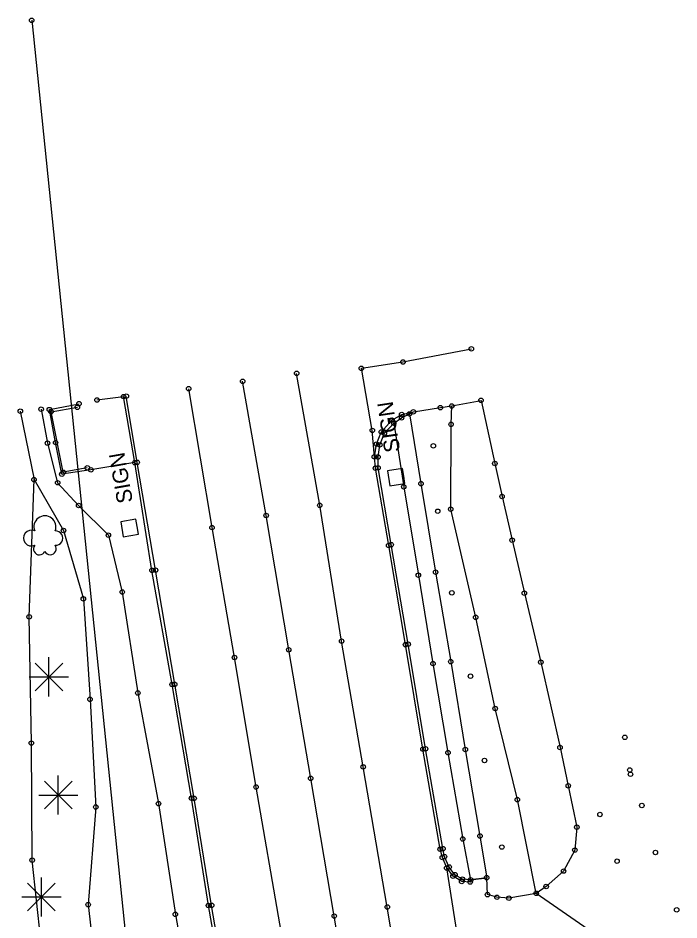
# Model space of a CAD drawing. Extents: x 21481721 to 21494985, y 8063982 to 8084842.
# Drawn here: x 21487996.8 to 21488144.4, y 8075524.3 to 8075725.6 of the extents above; entities that cross this region are included whole.
import ezdxf

# ---------------------------------------------------------------- set-up
doc = ezdxf.new("R2010")
doc.units = 0
for name, color, linetype in [('Building', 7, 'Continuous'), ('Drainage', 7, 'Continuous'), ('EXT_BL', 7, 'Continuous'), ('EXT_C', 7, 'Continuous'), ('EXT_CON', 7, 'Continuous'), ('EXT_CU', 7, 'Continuous'), ('EXT_GU', 7, 'Continuous'), ('EXT_SWK', 7, 'Continuous'), ('SurNaturalCells', 7, 'Continuous'), ('SurPointsNonDTM', 7, 'Continuous'), ('SurRoadPoints', 7, 'Continuous'), ('SurSurveyPoints', 7, 'Continuous')]:
    doc.layers.add(name, color=color, linetype=linetype)

msp = doc.modelspace()

# ---------------------------------------------------------------- linework, layer by layer
at = {"layer": 'Building'}
msp.add_lwpolyline([(21488012.29, 8075625.22), (21488006.93, 8075624.24), (21488004.19, 8075637.76), (21488010.07, 8075638.74)], dxfattribs=at)
at = {"layer": 'Drainage'}
msp.add_lwpolyline([(21487999.88, 8075725.11), (21488024.12, 8075488.97)], dxfattribs=at)
at = {"layer": 'EXT_BL'}
for points in [[(21488103.19, 8075384.64), (21488099.05, 8075409.52), (21488096.27, 8075426.26), (21488095.42, 8075431.16), (21488094.63, 8075436.26), (21488089.97, 8075465.06), (21488084.44, 8075496.32), (21488079.25, 8075527.2), (21488073.87, 8075558.48), (21488069.05, 8075586.55), (21488064.17, 8075616.87), (21488059.01, 8075646.31)], [(21488078.47, 8075383.41), (21488075.34, 8075404.11), (21488072.38, 8075422.27), (21488071.48, 8075427.29), (21488070.62, 8075432.22), (21488065.88, 8075460.89), (21488060.66, 8075491.95), (21488055.28, 8075523.45), (21488049.96, 8075553.99), (21488045.13, 8075582.91), (21488040.13, 8075611.89), (21488034.92, 8075642.89)], [(21487997.33, 8075637.86), (21488000.4, 8075622.59), (21488006.98, 8075611.23), (21488011.41, 8075595.98), (21488012.9, 8075573.56), (21488014.18, 8075549.52), (21488012.49, 8075527.74), (21488015.17, 8075504.07)], [(21488001.98, 8075638.33), (21488003.4, 8075630.75), (21488005.67, 8075621.9), (21488010.36, 8075616.83), (21488017, 8075610.19), (21488020.09, 8075597.51), (21488023.57, 8075574.98), (21488028.19, 8075550.29), (21488031.95, 8075525.57), (21488036.19, 8075501.31), (21488039.36, 8075478.97), (21488044.58, 8075454.12), (21488049.02, 8075430.98), (21488050.89, 8075415.65), (21488053.69, 8075400.59), (21488055.28, 8075390.26), (21488059.94, 8075389.21)], [(21488017.28, 8075334.44), (21488016.02, 8075354.14), (21488012.44, 8075377.08), (21488008.44, 8075400.23), (21488006.48, 8075416.6), (21488000.73, 8075439.94), (21487998.96, 8075464.83), (21488002.87, 8075510.86), (21487999.99, 8075537.67), (21487999.81, 8075563.8), (21487999.31, 8075591.97), (21488000.4, 8075622.59)]]:
    msp.add_lwpolyline(points, dxfattribs=at)
at = {"layer": 'EXT_C'}
msp.add_lwpolyline([(21488091.11, 8075383.97), (21488087.22, 8075407.72), (21488084.32, 8075424.42), (21488083.54, 8075429.23), (21488082.68, 8075434.22), (21488078.06, 8075462.54), (21488072.58, 8075494.16), (21488067.41, 8075525.19), (21488062.16, 8075555.92), (21488057.25, 8075584.62), (21488052.2, 8075614.6), (21488046.96, 8075644.54)], dxfattribs=at)
at = {"layer": 'EXT_CON'}
for points in [[(21488073.46, 8075647.44), (21488082.75, 8075648.86), (21488098.01, 8075651.79)], [(21488085.07, 8075637.72), (21488091.09, 8075638.67), (21488093.64, 8075639.04)], [(21488107.48, 8075477.19), (21488109.54, 8075479.35), (21488111.61, 8075481.3), (21488114.42, 8075483.32), (21488118.82, 8075485.97), (21488129.83, 8075487.79), (21488128.33, 8075497.11), (21488126.2, 8075509.77), (21488124.12, 8075522.17), (21488112.49, 8075530.26), (21488106.39, 8075529.17), (21488103.72, 8075529.39), (21488101.61, 8075529.97), (21488101.44, 8075533.75), (21488097.85, 8075533.27), (21488097.74, 8075532.79)]]:
    msp.add_lwpolyline(points, dxfattribs=at)
msp.add_lwpolyline([(21488112.49, 8075530.26), (21488108.29, 8075551.18), (21488103.34, 8075571.5), (21488098.98, 8075591.86), (21488093.41, 8075616.01), (21488093.49, 8075634.94), (21488093.64, 8075639.04), (21488100.18, 8075640.29), (21488103.27, 8075626.2), (21488104.87, 8075618.83), (21488107.11, 8075609.08), (21488109.85, 8075597.25), (21488113.51, 8075581.85), (21488117.8, 8075562.82), (21488119.64, 8075554.27), (21488121.56, 8075545.04), (21488121.12, 8075539.92), (21488118.6, 8075535.23), (21488114.71, 8075531.79)], close=True, dxfattribs=at)
at = {"layer": 'EXT_CU'}
for points in [[(21488055.5, 8075419.32), (21488055.16, 8075424.86), (21488054.72, 8075429.57), (21488053.7, 8075442.99), (21488050.75, 8075460.09), (21488047.06, 8075482.72), (21488043.37, 8075504.61), (21488039.33, 8075527.55), (21488035.55, 8075551.49), (21488031.22, 8075576.87), (21488026.72, 8075602.34), (21488022.88, 8075626.39), (21488020.38, 8075641.13)], [(21488097.85, 8075533.27), (21488096.02, 8075533.44), (21488094.35, 8075534.42), (21488093.06, 8075536.14), (21488092.02, 8075538.44), (21488091.68, 8075540.24), (21488087.8, 8075562.52), (21488083.91, 8075585.86), (21488080.11, 8075608.09), (21488077.18, 8075625.23), (21488077.18, 8075627.64), (21488077.57, 8075630.35), (21488078.61, 8075632.96), (21488080.69, 8075635.19), (21488082.44, 8075636.37), (21488085.07, 8075637.72)]]:
    msp.add_lwpolyline(points, dxfattribs=at)
at = {"layer": 'EXT_GU'}
for points in [[(21488076.36, 8075627.68), (21488075.91, 8075633.58), (21488073.46, 8075647.44)], [(21488056.32, 8075419.59), (21488055.81, 8075425.01), (21488055.29, 8075429.62), (21488055.5, 8075429.95), (21488054.21, 8075443.21), (21488051.26, 8075460.11), (21488047.59, 8075482.82), (21488043.93, 8075504.72), (21488040.04, 8075527.58), (21488036.13, 8075551.46), (21488031.81, 8075576.92), (21488027.53, 8075602.39), (21488023.43, 8075626.45), (21488020.99, 8075641.23)], [(21488097.74, 8075532.79), (21488095.86, 8075532.91), (21488093.93, 8075534.08), (21488092.51, 8075535.93), (21488091.54, 8075538.26), (21488091.05, 8075540.11), (21488087.22, 8075562.45), (21488083.3, 8075585.77), (21488079.56, 8075607.89), (21488076.6, 8075625.16), (21488076.36, 8075627.68), (21488076.83, 8075630.53), (21488077.91, 8075633.22), (21488080.29, 8075635.86), (21488082.46, 8075637.14), (21488085.07, 8075637.72)], [(21488103.55, 8075465.82), (21488102.57, 8075476.5), (21488099.84, 8075491.56), (21488097.64, 8075504.87), (21488094.91, 8075520.79), (21488092.51, 8075535.93)]]:
    msp.add_lwpolyline(points, dxfattribs=at)
at = {"layer": 'EXT_SWK'}
for points in [[(21488014.45, 8075640.38), (21488020.38, 8075641.13)], [(21488022.88, 8075626.39), (21488013.09, 8075624.79), (21488006.6, 8075623.81), (21488005.21, 8075630.86), (21488003.82, 8075638.23), (21488010.45, 8075639.54)], [(21488080.69, 8075635.19), (21488082.44, 8075636.37), (21488084.17, 8075637.26), (21488086.76, 8075621.7), (21488090.03, 8075601.95), (21488093.41, 8075581.98), (21488096.66, 8075562.36), (21488099.94, 8075543.05), (21488101.44, 8075533.75)], [(21488080.69, 8075635.19), (21488082.92, 8075621), (21488086.19, 8075601.26), (21488089.44, 8075581.54), (21488092.8, 8075561.67), (21488096.09, 8075542.39), (21488097.85, 8075533.27), (21488101.44, 8075533.75)]]:
    msp.add_lwpolyline(points, dxfattribs=at)
at = {"layer": 'SurNaturalCells'}
for p, q in [((21488003.71, 8075574.2), (21488003.71, 8075582.95)), ((21488000.62, 8075575.48), (21488006.8, 8075581.67)), ((21488006.8, 8075575.49), (21488000.62, 8075581.67)), ((21487999.34, 8075578.58), (21488008.08, 8075578.58)), ((21488003.71, 8075578.58), (21488003.71, 8075578.58)), ((21488005.82, 8075547.83), (21488005.82, 8075556.58)), ((21488002.73, 8075549.11), (21488008.91, 8075555.3)), ((21488008.91, 8075549.11), (21488002.73, 8075555.3)), ((21488001.45, 8075552.2), (21488010.2, 8075552.2)), ((21488005.82, 8075552.2), (21488005.82, 8075552.2)), ((21487998.97, 8075526.36), (21488005.15, 8075532.55)), ((21488005.15, 8075526.36), (21487998.97, 8075532.55)), ((21488002.06, 8075525.08), (21488002.06, 8075533.83)), ((21487997.69, 8075529.45), (21488006.43, 8075529.45)), ((21488002.06, 8075529.45), (21488002.06, 8075529.45))]:
    msp.add_line(p, q, dxfattribs=at)
for centre, radius, start, end in [((21488002.83, 8075612.06), 2.46, 338.2051, 201.7949), ((21487999.82, 8075609.55), 1.76, 65.4824, 294.5175), ((21488005.23, 8075609.55), 1.6, 265.9982, 94.0018), ((21488001.61, 8075607.14), 1.34, 142.7501, 335.3223), ((21488004.03, 8075607.18), 1.34, 206.5242, 35.4033)]:
    msp.add_arc(centre, radius, start, end, dxfattribs=at)
at = {"layer": 'SurPointsNonDTM'}
for centre in [(21487999.88, 8075725.11), (21488010.07, 8075638.74), (21488004.19, 8075637.76), (21488006.93, 8075624.24), (21488012.29, 8075625.22)]:
    msp.add_circle(centre, 0.5, dxfattribs=at)
at = {"layer": 'SurRoadPoints'}
for points in [[(21488082.94, 8075623.39), (21488082.94, 8075623.39), (21488082.68, 8075625.08), (21488079.29, 8075624.57), (21488079.8, 8075621.19), (21488083.19, 8075621.7), (21488082.94, 8075623.39)], [(21488023.41, 8075612.12), (21488023.41, 8075612.12), (21488023.11, 8075613.8), (21488019.74, 8075613.21), (21488020.33, 8075609.84), (21488023.7, 8075610.43), (21488023.41, 8075612.12)]]:
    msp.add_lwpolyline(points, dxfattribs=at)
at = {"layer": 'SurSurveyPoints'}
for centre in [(21488098.01, 8075651.79), (21488082.75, 8075648.86), (21488059.01, 8075646.31), (21488073.46, 8075647.44), (21488073.46, 8075647.44), (21488046.96, 8075644.54), (21488034.92, 8075642.89), (21488014.45, 8075640.38), (21488020.38, 8075641.13), (21488020.38, 8075641.13), (21488020.99, 8075641.23), (21488100.18, 8075640.29), (21488001.98, 8075638.33), (21488003.82, 8075638.23), (21488010.45, 8075639.54), (21488091.09, 8075638.67), (21488093.64, 8075639.04), (21488093.64, 8075639.04), (21487997.33, 8075637.86), (21488082.44, 8075636.37), (21488082.44, 8075636.37), (21488082.46, 8075637.14), (21488084.17, 8075637.26), (21488085.07, 8075637.72), (21488085.07, 8075637.72), (21488085.07, 8075637.72), (21488080.29, 8075635.86), (21488080.69, 8075635.19), (21488080.69, 8075635.19), (21488080.69, 8075635.19), (21488093.49, 8075634.94), (21488075.91, 8075633.58), (21488077.91, 8075633.22), (21488078.61, 8075632.96), (21488003.4, 8075630.75), (21488005.21, 8075630.86), (21488076.83, 8075630.53), (21488077.57, 8075630.35), (21488089.54, 8075630.14), (21488022.88, 8075626.39), (21488022.88, 8075626.39), (21488023.43, 8075626.45), (21488076.36, 8075627.68), (21488076.36, 8075627.68), (21488077.18, 8075627.64), (21488103.27, 8075626.2), (21488013.09, 8075624.79), (21488076.6, 8075625.16), (21488077.18, 8075625.23), (21488000.4, 8075622.59), (21488000.4, 8075622.59), (21488006.6, 8075623.81), (21488005.67, 8075621.9), (21488082.92, 8075621), (21488086.76, 8075621.7), (21488104.87, 8075618.83), (21488010.36, 8075616.83), (21488064.17, 8075616.87), (21488093.41, 8075616.01), (21488052.2, 8075614.6), (21488090.51, 8075615.54), (21488040.13, 8075611.89), (21488006.98, 8075611.23), (21488017, 8075610.19), (21488079.56, 8075607.89), (21488080.11, 8075608.09), (21488107.11, 8075609.08), (21488026.72, 8075602.34), (21488027.53, 8075602.39), (21488090.03, 8075601.95), (21488086.19, 8075601.26), (21488011.41, 8075595.98), (21488020.09, 8075597.51), (21488093.66, 8075597.33), (21488109.85, 8075597.25), (21487999.31, 8075591.97), (21488098.98, 8075591.86), (21488069.05, 8075586.55), (21488083.3, 8075585.77), (21488083.91, 8075585.86), (21488057.25, 8075584.62), (21488045.13, 8075582.91), (21488093.41, 8075581.98), (21488113.51, 8075581.85), (21488089.44, 8075581.54), (21488097.83, 8075578.72), (21488031.22, 8075576.87), (21488031.81, 8075576.92), (21488023.57, 8075574.98), (21488012.9, 8075573.56), (21488103.34, 8075571.5), (21487999.81, 8075563.8), (21488132.27, 8075565.09), (21488087.22, 8075562.45), (21488087.8, 8075562.52), (21488092.8, 8075561.67), (21488096.66, 8075562.36), (21488117.8, 8075562.82), (21488100.94, 8075559.92), (21488073.87, 8075558.48), (21488133.37, 8075557.78), (21488062.16, 8075555.92), (21488133.53, 8075556.84), (21488049.96, 8075553.99), (21488119.64, 8075554.27), (21488035.55, 8075551.49), (21488014.18, 8075549.52), (21488028.19, 8075550.29), (21488036.13, 8075551.46), (21488108.29, 8075551.18), (21488136.07, 8075549.87), (21488126.71, 8075547.87), (21488121.56, 8075545.04), (21488096.09, 8075542.39), (21488099.94, 8075543.05), (21488091.05, 8075540.11), (21488091.68, 8075540.24), (21488104.82, 8075540.59), (21488121.12, 8075539.92), (21487999.99, 8075537.67), (21488091.54, 8075538.26), (21488092.02, 8075538.44), (21488130.54, 8075537.43), (21488139.1, 8075539.39), (21488092.51, 8075535.93), (21488092.51, 8075535.93), (21488093.06, 8075536.14), (21488093.93, 8075534.08), (21488094.35, 8075534.42), (21488096.02, 8075533.44), (21488101.44, 8075533.75), (21488101.44, 8075533.75), (21488101.44, 8075533.75), (21488118.6, 8075535.23), (21488095.86, 8075532.91), (21488097.74, 8075532.79), (21488097.74, 8075532.79), (21488097.85, 8075533.27), (21488097.85, 8075533.27), (21488097.85, 8075533.27), (21488114.71, 8075531.79), (21488101.61, 8075529.97), (21488103.72, 8075529.39), (21488112.49, 8075530.26), (21488112.49, 8075530.26), (21488112.49, 8075530.26), (21488012.49, 8075527.74), (21488039.33, 8075527.55), (21488040.04, 8075527.58), (21488106.39, 8075529.17), (21488031.95, 8075525.57), (21488079.25, 8075527.2), (21488143.85, 8075526.59), (21488067.41, 8075525.19)]:
    msp.add_circle(centre, 0.5, dxfattribs=at)

# ---------------------------------------------------------------- texts
at = {"layer": 'SurRoadPoints'}
for rotation, p in [(98.5751, (21488082.14, 8075628.94)), (99.9237, (21488022.48, 8075617.64))]:
    msp.add_text('SIGN', height=3.498, rotation=rotation, dxfattribs=at).set_placement(p)

doc.saveas('drawing.dxf')
